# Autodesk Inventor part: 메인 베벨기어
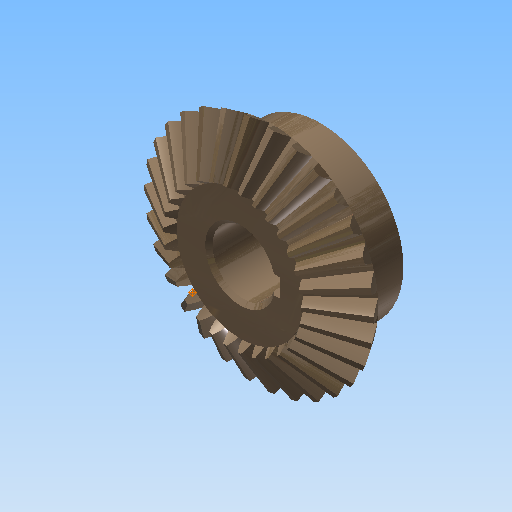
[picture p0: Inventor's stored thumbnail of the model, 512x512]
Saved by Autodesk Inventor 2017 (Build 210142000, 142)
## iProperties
Created: 2014-10
Part Number: 메인 베벨기어
Material: 강철, 탄소
Document SubType Name: Modeling
Designer: KYOUNG IL JANG
Categories: <?xml version="1.0" encoding="UTF-16"?> <MemberInstance><Categories><FamilyTemplate><FamilyTemplateParameter ValueType="xs:double" Id="1" ObjectReferenceKey="da
Mass: 269.926 g
Surface Area: 108.837 cm^2
Volume: 34.2981 cm^3
Density: 7.87 g/cm^3
Appearance: 얼룩무늬
CustomPartVersion: 1
Revision Number: 1
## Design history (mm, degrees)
node "맨 위 점"
node "메쉬 평면2"
sketch "톱니 본체 스케치"
  geometry: L1 (0, 0)-(28.669, -21.997); L2 (28.669, -21.997)-(31.109, -18.336); L3 (31.109, -18.336)-(0, 0); L4 (30, -20)-(0, 0); L5 (17.219, -13.212)-(18.685, -11.013); L6 (28.669, -21.997)-(17.219, -13.212); L7 (31.109, -18.336)-(18.685, -11.013); L8 (0, -39.387)-(0, 6.564) reference; L9 (0, -20)-(31.109, -20)
  constraints: 16 end point, 4 point on line, 3 perpendicular, 2 collinear, 1 horizontal alignment, 1 vertical alignment
  dimensions: "d0" = 60 diameter of L4.start L8 (= da_de); "d1" = 57.33744 diameter of L1.end L8 (= da_dfe); "d2" = 62.2188 diameter of L2.end L8 (= da_dae); "d3" = 14.4 distance between parallel lines of L2 L5 (= da_b); "d4" = 18.3359 vertical distance of L2.end L1.start (= da_ve)
revolve "톱니 본체" sketch "톱니 본체 스케치" stored, may be unused: angle "d5" = 90 deg
node "시작점"
node "톱니 평면"
sketch "시작 스케치"
  geometry: L1 (0, -23.505)-(0, 10.645) reference; L2 (-0.709, -2.928)-(0.709, -2.928); A1 r 19.188 centre (-19.457, -7.014) between (-0.709, -2.928) and (-3.232, 3.229); A2 r 19.188 centre (19.457, -7.014) between (3.232, 3.229) and (0.709, -2.928); A3 r 57.403 centre (0, -54.083) between (3.232, 3.229) and (-3.232, 3.229); 1 further point
  constraints: 6 point on circle, 3 centre point, 3 symmetric about line, 2 end point, 1 coincident, 1 perpendicular, 1 other
  dimensions: "d7" = 19.18795 radius of A1 (= fd_rr); "d8" = 19.45712 horizontal distance of point (0, -54.083) A1.centre (= fd_x); "d9" = 47.06905 vertical distance of point (0, -54.083) A1.centre (= fd_y); "d57" = 57.40327 radius of A3 (= 0.5 x fd_dva + 0.3 x da_he); "d58" = 51.15527 distance from line of A3.centre L2 (= 0.5 x fd_dva - 1.12 x da_he)
node "끝점"
  node "끝 평면"
sketch "3D 스케치 오른쪽"
  node "Helical Curve Right" dims "d65" = 229.90621 (computed from da_dm, da_delta, da_beta), "d66" = 31.5, "d67" = 60 (= da_de), "d68" = -9.82794 (= -da_delta), "d69" = 8.10972 (computed from fd_loft, da_delta)
node "끝 평면 오른쪽"
sketch "끝 스케치 오른쪽"
  geometry: L1 (0, -41.54)-(0, 13.178) reference; L2 (-0.422, -1.69)-(0.422, -1.69); A1 r 11.427 centre (-11.587, -4.123) between (-0.422, -1.69) and (-1.925, 1.977); A2 r 11.427 centre (11.587, -4.123) between (1.925, 1.977) and (0.422, -1.69); A3 r 34.184 centre (0, -32.153) between (1.925, 1.977) and (-1.925, 1.977); 1 further point
  constraints: 6 point on circle, 3 centre point, 3 symmetric about line, 2 end point, 1 coincident, 1 perpendicular, 1 other
  dimensions: "d70" = 11.58699 horizontal distance of A3.centre A1.centre (computed from fd_x, fd_ratio); "d71" = 28.03028 vertical distance of point (0, -32.153) A1.centre (computed from fd_y, fd_ratio); "d72" = 11.4267 radius of A1 (computed from fd_rr, fd_ratio); "d73" = 30.46369 distance from line of point (0, -32.153) L2 (computed from d58, fd_ratio); "d74" = 34.18446 radius of A3 (computed from d57, fd_ratio)
feature "로프트 오른쪽" sketch "끝 스케치 오른쪽" dims "d75" = 0, "d77" = 0, "d79" = 0, "d80" = 90 deg, "d85" = 20, "d92" = 90 deg, "d93" = 90 deg, "da_teethtype" = 0 [user parameter]
sketch "3D 스케치 왼쪽"
  node "Helical Curve Left" dims "d26" = 229.90621 (computed from da_dm, da_delta, da_beta), "d27" = 8.10972 (computed from fd_loft, da_delta), "d28" = 60 (= da_de), "d29" = -9.82794 (= -da_delta)
node "끝 평면 왼쪽"
sketch "끝 스케치 왼쪽" dims "d56" = 10.3728 (derived)
  geometry: L1 (0, -43.753)-(0, 15.405) reference; L2 (-0.422, -1.678)-(0.422, -1.678); A1 r 11.427 centre (-11.587, -4.111) between (-0.422, -1.678) and (-1.925, 1.988); A2 r 11.427 centre (11.587, -4.111) between (1.925, 1.988) and (0.422, -1.678); A3 r 34.184 centre (0, -32.142) between (1.925, 1.988) and (-1.925, 1.988); 2 further points; 1 other entity
  constraints: 6 point on circle, 3 centre point, 3 symmetric about line, 2 end point, 1 coincident, 2 other
  dimensions: "d30" = 11.4267 radius of A1 (computed from fd_rr, fd_ratio); "d31" = 11.58699 horizontal distance of point (0, -32.142) A1.centre (computed from fd_x, fd_ratio); "d32" = 28.03028 vertical distance of A1.centre point (0, -32.142) (computed from fd_y, fd_ratio); "d61" = 34.18446 radius of A3 (computed from d57, fd_ratio); "d62" = 30.46369 distance from line of point (0, -32.142) L2 (computed from d58, fd_ratio)
feature "로프트 왼쪽" sketch "끝 스케치 왼쪽" dims "d35" = 0, "d37" = 0, "d39" = 0, "d40" = 90 deg, "d84" = 10, "d90" = 90 deg, "d91" = 90 deg, "da_teethtype" = 0 [user parameter]
sketch "본체 스케치"
  geometry: L1 (0, -35.038)-(0, -19.531) reference; L2 (28.669, -21.997)-(17.219, -13.212) reference; L3 (17.219, -13.212)-(0, -13.212); L4 (28.669, -21.997)-(0, -21.997)
  constraints: 4 end point, 2 perpendicular, 2 point on line
revolve "본체 고정" sketch "본체 스케치" stored, may be unused: angle "d46" = 90 deg
feature "피치 지름" dims angle "d47" = 90 deg
sketch "스케치8"
  geometry: C1 r 22.5 at (0, 0); 1 further point
  constraints: 1 centre point, 1 coincident
  dimensions: "d94" = 45 diameter of C1
extrude "돌출1" join sketch "스케치8" distance "d95" = 13; taper "d96" = 0 deg
sketch "스케치9"
  geometry: 1 further point
hole "구멍1" sketch "스케치9" at (0, 0) diameter "d97" = 17; stored, may be unused: countersink angle "d101" = 90 deg, drill point angle "d103" = 118 deg; dims "d98" = 6, "d99" = 4, "d100" = 2, "d102" = 8
sketch "스케치10"
  geometry: L1 (8.124, 2.5)-(10.8, 2.5); L2 (10.8, 2.5)-(10.8, -2.5); L3 (10.8, -2.5)-(8.124, -2.5); A1 r 8.5 centre (0, 0) between (8.124, 2.5) and (8.124, -2.5) reference; 1 further point
  constraints: 6 end point, 2 parallel, 2 point on circle, 1 horizontal, 1 perpendicular
  dimensions: "d104" = 5 distance of L1.end L2.end; "d112" = 19.3 dimension on A1 L2
extrude "돌출2" cut sketch "스케치10" stored distance "d106" = 10; taper "d107" = 0 deg
chamfer "모따기1" distance "d108" = 1; stored, may be unused: second distance "d109" = 2, angle "d110" = 45 deg
fillet "모깎기1" dims "d111" = 2
body "Solid1"
feature "로프트" dims "d17" = 0, "d18" = 90 deg, "d19" = 0, "d20" = 90 deg, "d89" = 0, "da_teethtype" = 0 [user parameter]
pattern_circular "원형 패턴" dims angle "d22" = 360 deg, "d88" = 0, "da_teethtype" = 0 [user parameter]
pattern_circular "원형 패턴 오른쪽" dims angle "d82" = 360 deg, "da_teethtype" = 0 [user parameter]
pattern_circular "원형 패턴 왼쪽" dims angle "d42" = 360 deg, "da_teethtype" = 0 [user parameter]
sketch "끝 스케치"
  geometry: L1 (0, -15.359)-(0, 6.983) reference; L2 (-0.422, -1.69)-(0.422, -1.69); A1 r 11.427 centre (-11.587, -4.123) between (-0.422, -1.69) and (-1.925, 1.977); A2 r 11.427 centre (11.587, -4.123) between (1.925, 1.977) and (0.422, -1.69); A3 r 34.184 centre (0, -32.153) between (1.925, 1.977) and (-1.925, 1.977); 1 further point
  constraints: 6 point on circle, 3 centre point, 3 symmetric about line, 2 end point, 1 coincident, 1 other
  dimensions: "d12" = 11.4267 radius of A1 (computed from fd_rr, fd_ratio); "d15" = 11.58699 horizontal distance of A1.centre point (0, -32.153) (computed from fd_x, fd_ratio); "d16" = 28.03028 vertical distance of A1.centre point (0, -32.153) (computed from fd_y, fd_ratio); "d59" = 34.18446 radius of A3 (computed from d57, fd_ratio); "d60" = 30.46369 distance from line of A3.centre L2 (computed from d58, fd_ratio)
sketch "Sketch6"
  geometry: L1 (30, -20)-(0, 0) reference; L2 (0, -37.8)-(0, 6.3) reference
body "Srf1"
other parameters: "da_b" = 14.4 [user parameter; used in 2 equation terms], "da_de" = 60 [user parameter; used in 4 equation terms], "da_dae" = 62.2188 [user parameter; used in 2 equation terms], "da_dfe" = 57.33744 [user parameter; used in 1 equation term], "da_le" = 36.05551 [user parameter; used in 1 equation term], "da_omega" = 90 deg [user parameter; used in 1 equation term], "da_beta" = 0 [user parameter; used in 2 equation terms], "da_delta" = 9.82794 [user parameter; used in 8 equation terms], "da_alpha" = 20 deg [user parameter; used in 2 equation terms], "da_he" = 4.4 [user parameter; used in 4 equation terms], "da_ve" = 18.3359 [user parameter; used in 1 equation term], "fd_dv" = 108.16654 (computed from da_de, da_delta) [user parameter; used in 1 equation term], "fd_dva" = 112.16654 (computed from da_dae, da_delta) [user parameter; used in 3 equation terms], "fd_dvb" = 101.6433 (computed from fd_dv, da_alpha) [user parameter; used in 2 equation terms], "da_zv" = 540.83269 [user parameter; used in 1 equation term], "fd_loft" = 14.62 (= da_b + 0.05 x da_he) [user parameter; used in 4 equation terms], "fd_ratio" = 5.95514 (computed from da_le, fd_loft) [user parameter; used in 15 equation terms], "fd_rr" = 19.18795 (computed from fd_dd, fd_dvb) [user parameter; used in 6 equation terms], "fd_angle" = 0.29367 (computed from da_zv) [user parameter; used in 4 equation terms], "fd_x1" = 1.58802 (computed from da_dvw, fd_angle) [user parameter; used in 1 equation term], "fd_y1" = 54.05995 (computed from da_dvw, fd_angle) [user parameter; used in 1 equation term], "fd_x2" = 17.8691 (computed from fd_rr, fd_angle2, fd_angle) [user parameter; used in 1 equation term], "fd_y2" = 6.9909 (computed from fd_rr, fd_angle2, fd_angle) [user parameter; used in 1 equation term], "fd_x" = 19.45712 (= fd_x1 + fd_x2) [user parameter; used in 4 equation terms], "fd_y" = 47.06905 (= fd_y1 - fd_y2) [user parameter; used in 4 equation terms], "fd_angle2" = 3.43555 (computed from fd_dvb, fd_dd, da_alpha) [user parameter; used in 2 equation terms], "fd_dd" = 108.64654 (= fd_dva - 0.8 x da_he) [user parameter; used in 2 equation terms], "da_dvw" = 108.16654 [user parameter; used in 2 equation terms], "d11" = 14.62 (= fd_loft), "da_dm" = 48.01848 [user parameter; used in 2 equation terms], "da_x" = 0 [user parameter], "da_m" = 2 [user parameter], "d48" = 0, "d49" = 0, "d50" = 90 deg (= da_omega), "d51" = 6 deg (computed from da_z), "d52" = 0, "d53" = 0, "d54" = 0
